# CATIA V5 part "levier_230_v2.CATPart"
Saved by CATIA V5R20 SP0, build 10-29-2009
Part number: levier_230
Bounding box of the stored display mesh (mm): x -60 to 20, y -55 to 205, z -14.986 to 14.986
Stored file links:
  D:\thinkmotion-MPB\Dropbox\IAO_2011\MMS_GR3\aweinling\aweinling\levier_230_v2.CATPart
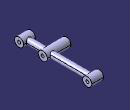
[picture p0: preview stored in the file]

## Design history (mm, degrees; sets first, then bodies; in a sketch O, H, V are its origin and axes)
Parameters
  `Longueur L1` = 80 mm
  `Longueur L2` = 150 mm
  `Largeur La` = 40 mm
  D_Bielle = 20 mm
  D_Trou = 10 mm
  D_Pivot = 30 mm
Body1 (main body)
  Sketch1 on yz-plane, origin (0, 0, 0), H (0, 1, 0), V (0, 0, 1)
    circle A1 centre (-40, 0) radius 15
    point P1 (-40, 0)
    circle A2 centre (190, 0) radius 15
    point P2 (190, 0)
    point P3 (40, 0)
    radius A1 = 15 {= D_Pivot /2}
    radius A2 = 15 {= D_Pivot /2}
    distance P1 P3 = 80 {= `Longueur L1`}
    distance P1 O = 40 {= `Longueur L1` /2}
    distance P3 P2 = 150 {= `Longueur L2`}
    coincidence: P3 H
  Pad1: profile Sketch1, direction (1, 0, 0), length 20 {= `Largeur La` /2}, mirrored extent
  Sketch2 on yz-plane, origin (0, 0, 0), H (0, 1, 0), V (0, 0, 1)
    circle A1 centre (40, 0) radius 15
    point P1 (40, 0)
    radius A1 = 15 {= D_Pivot /2}
    distance P1 O = 40 {= `Longueur L1` /2}
    coincidence: P1 H
  Pad2: profile Sketch2, direction (1, 0, 0), length 20, opposite side length 60 {= `Largeur La` *1.5}
  Sketch3 on zx-plane, origin (0, 0, 0), H (-1, 0, 0), V (0, 0, 1)
    circle A1 centre (0, 0) radius 10
    radius A1 = 10 {= D_Bielle /2}
  Pad3: profile Sketch3, direction (0, 1, 0), length 40 {= `Longueur L1` /2}, mirrored extent
  Sketch4 on xy-plane, origin (0, 0, 0), H (1, 0, 0), V (0, 1, 0)
    point P1 (0, 40)
    line L1 (0, 40) -> (10, 40)
    line L2 (10, 40) -> (10, 190)
    line L3 (10, 190) -> (0, 190)
    line L4 (0, 190) -> (0, 40)
    distance L4 L2 = 10 {= D_Bielle /2}
    distance L1 L3 = 150 {= `Longueur L2`}
    coincidence: P1 V
    horizontal: L1 H, L3 H
    vertical: L2 V, L4 V
  Shaft1: profile Sketch4, axis Sketch4.L4, angle 360
  Sketch5 on end face of Pad1, origin (20, -29.9053, 4.6353), H (0, 1, 0), V (0, 0, 1)
    point P1 (-10.0947, -4.6353)
    reference projected circle E1 centre (-10.0947, -4.6353) radius 15 from edge [face of Pad1 from Sketch1.A1 | end face of Pad1]
    concentricity: P1 E1
  Hole1: placed by Sketch5, at (20, -40, 0) direction (-1, 0, 0), diameter 10 {= D_Trou}, through (limit type 3)
  Sketch6 on end face of Pad2, origin (20, 40, 0), H (0, 1, 0), V (0, 0, 1)
    point P1 (0, 0)
    reference projected circle E1 centre (0, 0) radius 15 from edge [face of Pad2 from Sketch2.A1 | end face of Pad2]
    concentricity: P1 E1
  Hole2: placed by Sketch6, at (20, 40, 0) direction (-1, 0, 0), diameter 10 {= D_Trou}, through (limit type 3)
  Sketch7 on end face of Pad1, origin (20, 190.0195, 2.3727), H (0, 1, 0), V (0, 0, 1)
    point P1 (-0.0195, -2.3727)
    reference projected circle E1 centre (-0.0195, -2.3727) radius 15 from edge [face of Pad1 from Sketch1.A2 | end face of Pad1]
    concentricity: P1 E1
  Hole3: placed by Sketch7, at (20, 190, 0) direction (-1, 0, 0), diameter 10 {= D_Trou}, through (limit type 3)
